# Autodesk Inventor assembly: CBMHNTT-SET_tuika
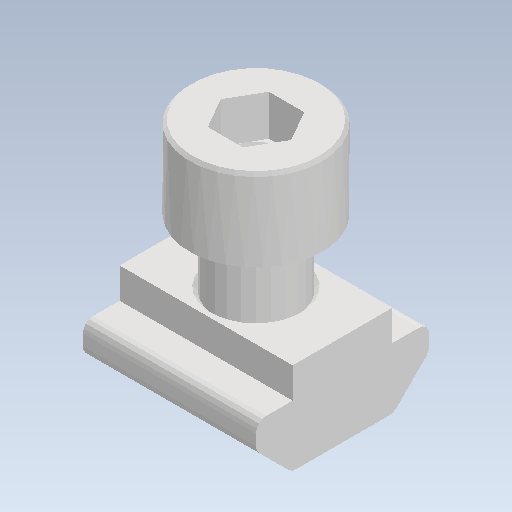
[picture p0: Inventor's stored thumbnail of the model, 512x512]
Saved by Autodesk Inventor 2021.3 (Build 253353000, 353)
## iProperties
Created: 2022-02
Part Number: CBMHNTT-SET_tuika
Document SubType Name: Assembly
Designer: kengo
Author: kengo
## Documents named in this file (3)
- C:\Users\kengo\Documents\S2S_frame\SDC345\frame_misumi_ver12\CBMHNTT-SET_tuika.iam
- C:\Users\kengo\Documents\S2S_frame\SDC345\frame_misumi_ver12\HNTT8-8.ipt
- C:\Users\kengo\Documents\S2S_frame\SDC345\frame_misumi_ver12\CBM8-15.ipt
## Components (2 placed, 2 different names)
1. HNTT8-8:3
2. CBM8-15:3
